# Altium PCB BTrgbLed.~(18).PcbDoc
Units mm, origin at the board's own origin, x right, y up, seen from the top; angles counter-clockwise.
Board outline 98.71 x 98.67 mm, 2 copper layers (Top Layer, Bottom Layer); 13 components, 12 nets, 62 pads, 4 vias.
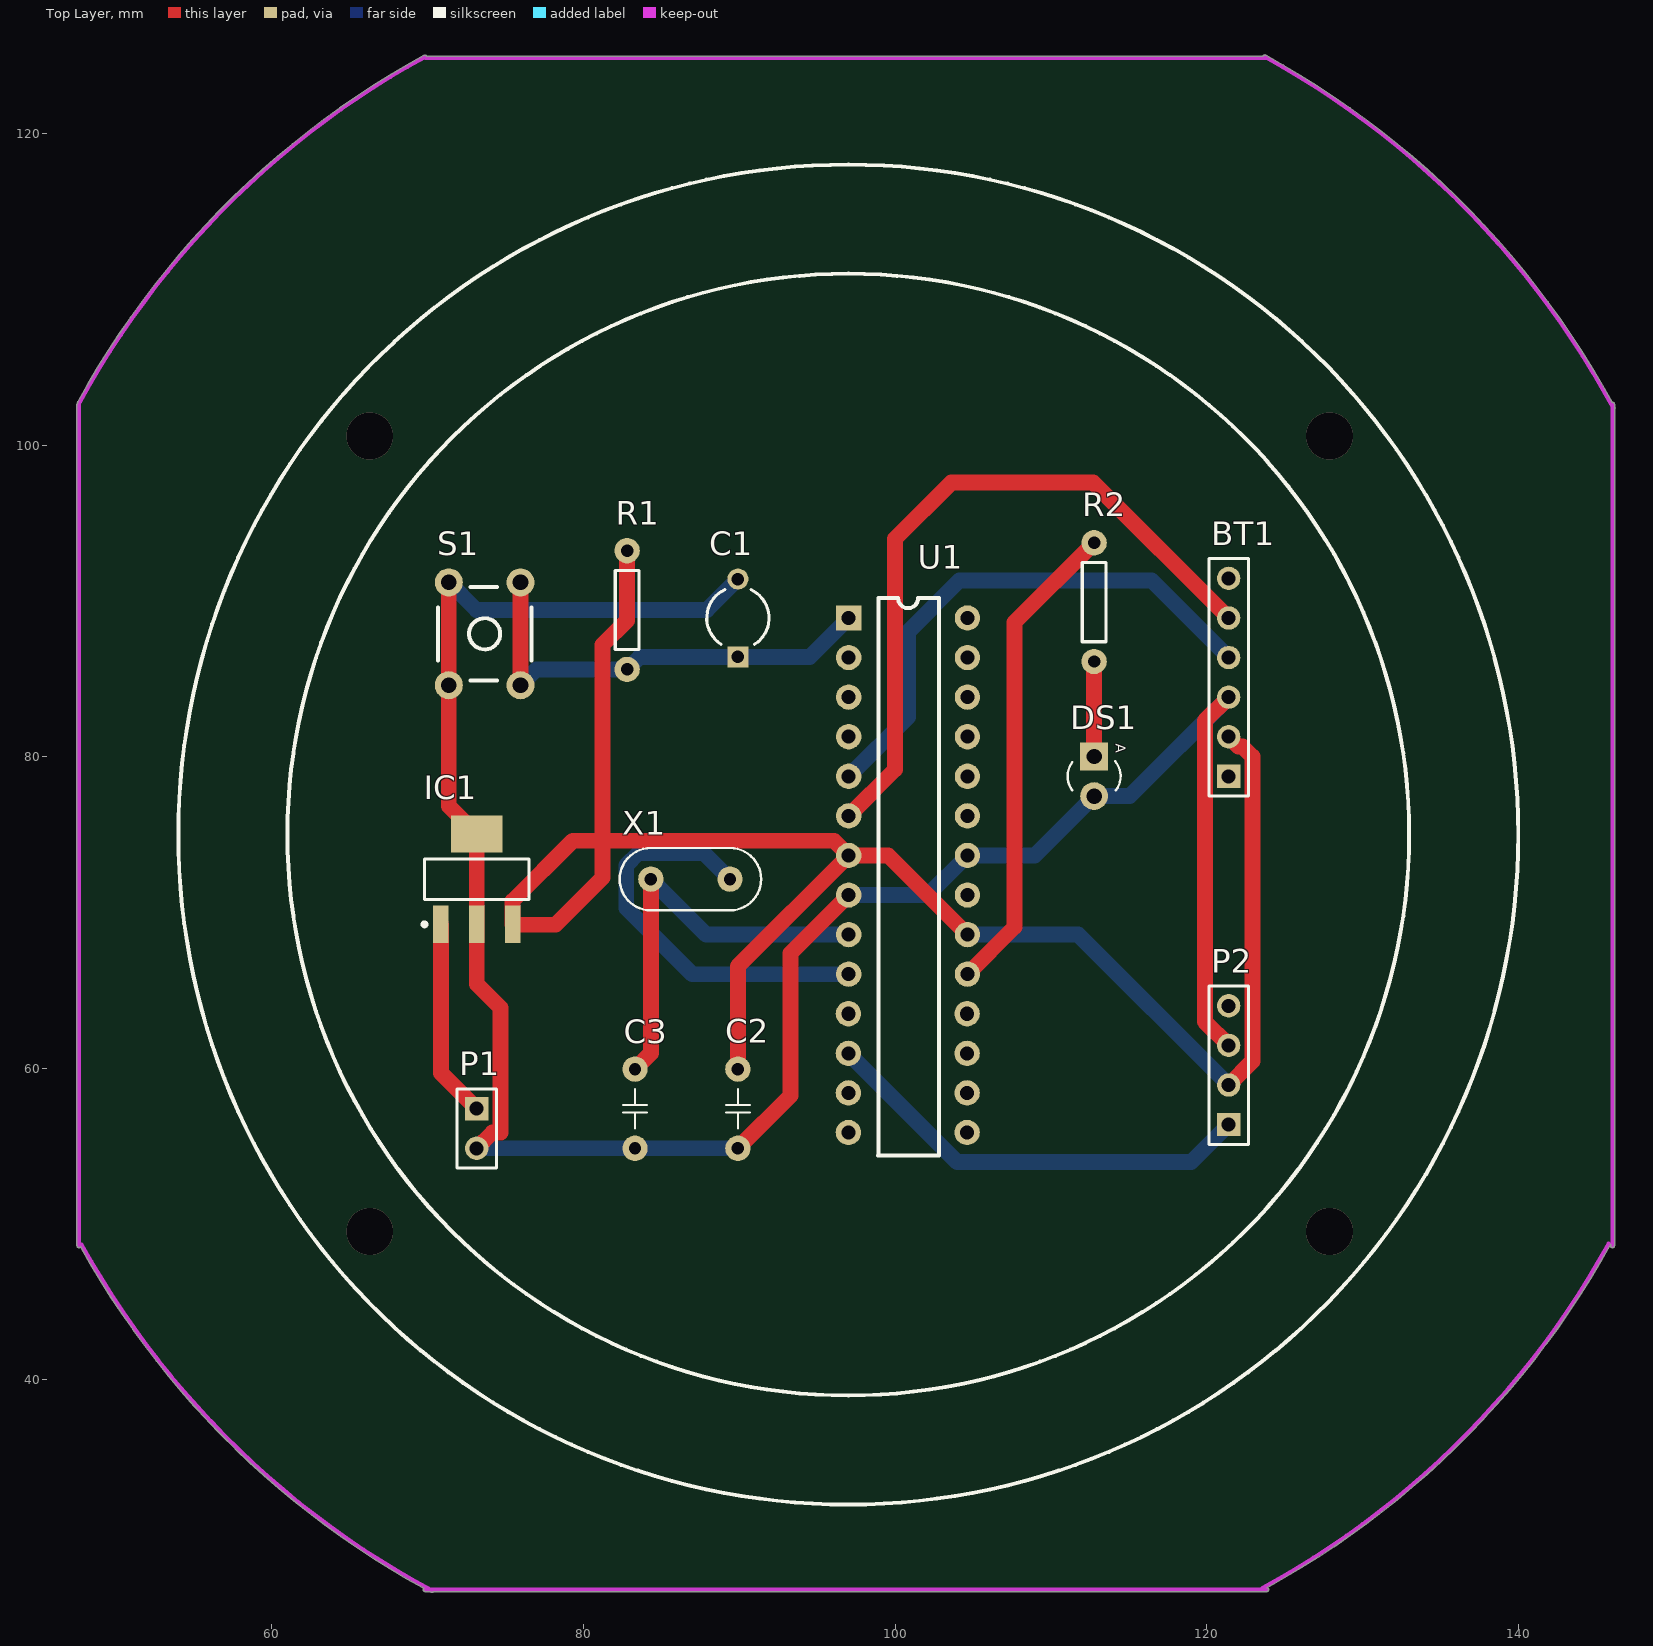
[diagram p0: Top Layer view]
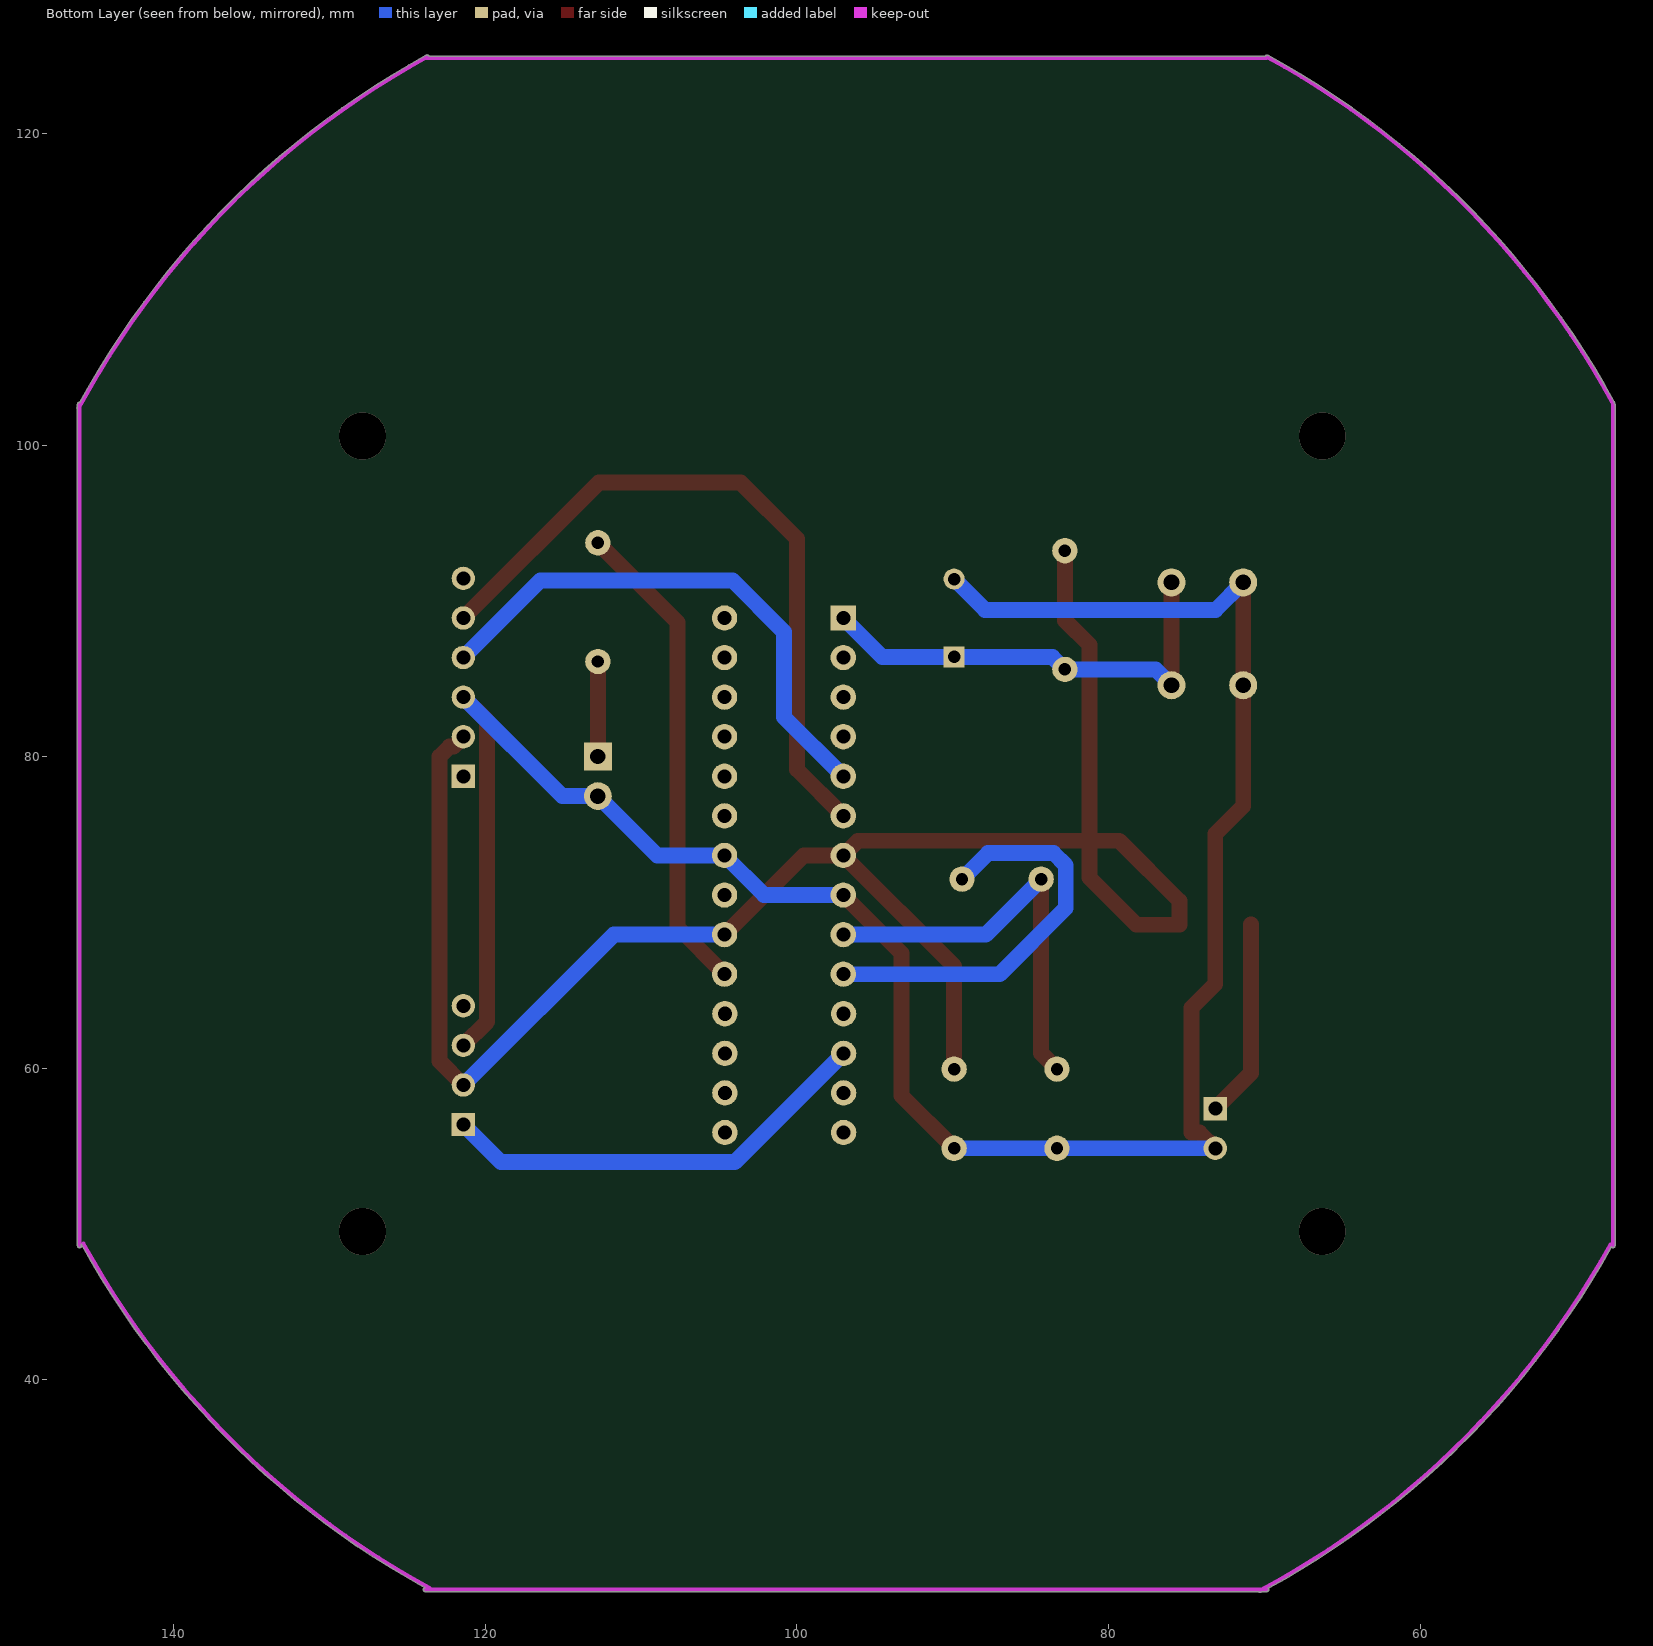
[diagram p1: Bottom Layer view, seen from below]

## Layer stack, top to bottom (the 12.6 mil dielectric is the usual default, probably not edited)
Top Layer: signal copper 0.0356
Dielectric: dielectric 0.32, FR-4, Dk 4.8
Bottom Layer: signal copper 0.0356

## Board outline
69.85,26.416 70.143,26.416 ccw(c96.781,75.819) 70.218,26.375 ccw(c70.279,26.487) 70.384,26.416 123.85,26.416 ccw(c123.85,26.543) 123.977,26.543 ccw(c123.85,26.543) 123.88,26.667 ccw(c96.781,75.819) 145.916,48.69 ccw(c145.805,48.751) 145.923,48.703 145.923,48.616 ccw(c146.05,48.616) 146.177,48.616 146.177,102.295 ccw(c146.082,102.379) 146.209,102.379 ccw(c146.082,102.379) 146.194,102.44 ccw(c96.781,75.819) 146.177,102.47 146.177,102.616 ccw(c146.05,102.616) 146.03,102.742 ccw(c96.781,75.819) 123.795,125.018 ccw(c123.734,124.906) 123.623,124.968 69.925,124.968 ccw(c69.817,124.9) 69.756,125.012 ccw(c96.781,75.819) 47.559,102.791 ccw(c47.671,102.73) 47.544,102.715 ccw(c47.625,102.616) 47.498,102.616 47.498,48.616 ccw(c47.625,48.616) 47.728,48.541 ccw(c96.781,75.819) 69.754,26.627 ccw(c69.85,26.543)

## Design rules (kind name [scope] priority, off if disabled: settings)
Clearance [All] p1: gap=0.254
PolygonConnect [All] p1: connectstyle=Relief reliefconductorwidth=0.254 reliefentries=4 polygonreliefangle="90 Angle"
RoutingVias [All] p1: holewidth=0.711 width=1.27 viastyle="Through Hole" minholewidth=0.711 minwidth=1.27 maxholewidth=0.711 maxwidth=1.27
SilkscreenOverComponentPads [All] p1: minsilkscreentomaskgap=0.254
SolderMaskExpansion [All] p1: expansion=0.102
Width [All] p1: maxlimit=1.27 minlimit=0.762 preferedwidth=1.016
27 further rules are at their usual default settings.

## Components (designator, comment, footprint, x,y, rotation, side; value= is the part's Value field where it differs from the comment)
BT1 "Bluetooth" Bluetooth 121.412,78.74 r90 top
C1 "47uF" CAPR5-4X5 89.916,88.9 r90 top
C2 "22pF" C200 89.916,57.404 r0 top
C3 "22pF" C200 83.312,57.404 r180 top
DS1 "TX-LED" LED-3mm_G 112.776,78.74 r270 top
IC1 "AM1117-5V" SOT-223 73.152,72.136 r90 top
P1 "12V" HDR1X2 73.152,57.404 r270 top
P2 "環形LED燈" HDR1X4 121.412,56.388 r90 top
R1 "10k" AXIAL-0.3 82.804,89.408 r270 top
R2 "220" AXIAL-0.3 112.776,89.916 r90 top
S1 "SW-PB" TACK6 73.66,87.884 r90 top
U1 "ATmega328" DIP-28 97.028,88.9 r270 top
X1 "16MHz" XTAL4-8 86.868,72.136 r0 top

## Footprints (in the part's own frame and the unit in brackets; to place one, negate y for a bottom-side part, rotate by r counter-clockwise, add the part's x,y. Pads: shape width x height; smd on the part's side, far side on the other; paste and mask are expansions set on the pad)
AXIAL-0.3 [mil] "0.3\" Resistor; 2 Leads"
  round 64 hole 31.5: 1(-150,0) 2(150,0)
  silkscreen extent -100,-30 100,30, body extent -161,-39 165,39, height 86
Bluetooth [mm]
  rect 1.5x1.5 hole 0.9: 1(0,0)
  round 1.5 hole 0.9: 2(2.54,0) 3(5.08,0) 4(7.62,0) 5(10.16,0) 6(12.7,0)
  silkscreen extent -1.27,-1.27 13.97,1.27, body extent -1.25,-1.3 13.97,1.28, height 11
C200 [mil] "塑膠電容器"
  round 64 hole 31.5: 1(0,100) 2(0,-100)
  silkscreen extent -30,-50 30,50, body extent -41,-136 39,135, height 354
CAPR5-4X5 [mm] "Capacitor; 2 Leads"
  rect 1.35x1.35 hole 0.8: 1(-2.5,0)
  round 1.35 hole 0.8: 2(2.5,0)
  silkscreen extent -1.69,-2 1.82,2
DIP-28 [mil]
  rect 64x64 hole 35.43: 1(0,0)
  round 64 hole 35.43: 2(100,0) 3(200,0) 4(300,0) 5(400,0) 6(500,0) 7(600,0) 8(700,0) 9(800,0) 10(900,0) 11(1000,-0.79) 12(1100,-0.79) 13(1200,-0.79) 14(1300,-0.79) 15(1300,299.21) 16(1200,299.21) 17(1100,299.21) 18(1000,299.21) 19(900,300) 20(800,300) 21(700,300) 22(600,300) 23(500,300) 24(400,300) 25(300,300) 26(200,300) 27(100,300) 28(0,300)
  silkscreen extent -50,74 1358,228, body extent -53,-5 1358,304, height 209
HDR1X2 [mm] "Connector; Header; 2 Position"
  rect 1.5x1.5 hole 0.9: 1(0,0)
  round 1.5 hole 0.9: 2(2.54,0)
  silkscreen extent -1.27,-1.27 3.81,1.27
HDR1X4 [mm] "Connector; Header; 4 Position"
  rect 1.5x1.5 hole 0.9: 1(0,0)
  round 1.5 hole 0.9: 2(2.54,0) 3(5.08,0) 4(7.62,0)
  silkscreen extent -1.27,-1.27 8.89,1.27
LED-3mm_G [mil] "3mm LED_Green"
  rect 70x70 hole 39: 1(-50,0)
  round 70 hole 39: 2(50,0)
  silkscreen extent -38,-67 35,67, body extent -66,-68 67,66, height 181
SOT-223 [mm] "SOT223, 4-Leads, Body 6.7x7.3mm (max), Pitch 2.30mm, IPC Medium Density"
  rect 2.4x1 smd: 1(-2.9,2.3) 2(-2.9,0) 3(-2.9,-2.3)
  rect 2.4x3.3 smd: 2(2.9,0)
  silkscreen extent -3.02,-3.35 1.3,3.47, body extent -1.86,-3.35 1.86,3.35, height 1.8
TACK6 [mm]
  round 1.8 hole 1: 1(-3.3,2.3) 1(3.3,2.3) 2(-3.3,-2.3) 2(3.3,-2.3)
  silkscreen extent -3,-3 3,3, body extent -3,-3.01 3.08,3.04, height 8
XTAL4-8 [mil]
  round 64 hole 31.5: 1(-100,0) 2(100,0)
  silkscreen extent -179,-79 179,79, body extent -178,-80 192,79, height 157

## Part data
C1: library part "Cap Pol1", "Polarized Capacitor (Radial)"
C2 C3: library part Cap, "Capacitor"
DS1: library part LED, "Typical INFRARED GaAs LED"
IC1: library part AM1117
P1: library part "Header 2", "Header, 2-Pin"
P2: library part "Header 4", "Header, 4-Pin"
R1 R2: library part Res, "Resistor"
S1: "Switch"
U1: "Arduino"
X1: library part XTAL, "Crystal Oscillator"

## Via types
v1: diameter 3, hole 3, Top Layer to Bottom Layer, 4 vias

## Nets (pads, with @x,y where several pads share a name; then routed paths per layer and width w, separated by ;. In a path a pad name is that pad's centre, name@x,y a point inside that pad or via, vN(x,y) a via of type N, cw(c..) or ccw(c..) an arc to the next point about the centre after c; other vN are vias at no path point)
DI: P2.1 U1.12 | length 28.3
  Bottom Layer w1.016: U1.12 103.993,53.975 118.999,53.975 P2.1
DO: P2.4
GND: BT1.3 C1.2 C2.2 C3.1 DS1.2 IC1.2 P1.2 P2.3 S1.1 U1.8 U1.22 | length 148
  Top Layer w1.016: S1.1@71.36,91.184 71.36,84.584 71.36,76.828 73.152,75.036 73.152,69.236 73.152,65.405 74.676,63.881 74.676,55.88 74.168,55.88 P1.2 ; C2.2 93.294,58.242 93.294,67.386 U1.8 ; P2.3 119.888,62.992 119.888,82.296 BT1.3
  Bottom Layer w1.016: S1.1@71.36,91.184 73.136,89.408 87.924,89.408 C1.2 ; P1.2 C3.1 C2.2 ; U1.8 102.108,71.12 U1.22 108.966,73.66 DS1.2 115.062,77.47 BT1.3
NetC1_1: C1.1 R1.2 S1.2 U1.1 | length 29.5
  Top Layer w1.016: S1.2@75.96,84.584 S1.2@75.96,91.184
  Bottom Layer w1.016: S1.2@75.96,84.584 76.974,85.598 R1.2 83.606,86.4 C1.1 94.528,86.4 U1.1
NetC2_2: U1.10 X1.2 | length 26.5
  Bottom Layer w1.016: X1.2 87.732,73.812 83.541,73.812 82.753,73.025 82.753,70.282 86.995,66.04 U1.10
NetC3_2: C3.2 U1.9 X1.1 | length 26.8
  Top Layer w1.016: C3.2 84.328,60.96 X1.1
  Bottom Layer w1.016: X1.1 87.884,68.58 U1.9
NetDS1_1: DS1.1 R2.1 | length 6.1
  Top Layer w1.016: DS1.1 R2.1
NetIC1_1: IC1.1 P1.1 | length 12.8
  Top Layer w1.016: IC1.1 70.852,59.704 P1.1
NetR2_2: R2.2 U1.19 | length 31.1
  Top Layer w1.016: U1.19 107.671,69.063 107.671,88.621 R2.2
RX: BT1.5 U1.6 | length 45.5
  Top Layer w1.016: U1.6 100,79.172 100,93.98 103.607,97.587 112.725,97.587 BT1.5
TX: BT1.4 U1.5 | length 34.8
  Bottom Layer w1.016: U1.5 100.838,82.55 100.838,88.011 104.14,91.313 116.459,91.313 BT1.4
VCC: BT1.2 C2.1 IC1.3 P2.2 R1.1 U1.7 U1.20 | length 124.7
  Top Layer w1.016: R1.1 82.804,88.748 81.229,87.173 81.229,74.6 ; C2.1 89.916,66.548 U1.7 ; U1.20 99.568,73.66 U1.7 ; P2.2 122.936,60.452 122.936,80.01 122.301,80.645 122.047,80.645 BT1.2 ; 81.229,74.6 96.088,74.6 U1.7 ; 81.229,74.6 79.313,74.6 75.452,70.739 IC1.3 75.452,69.215 78.207,69.215 81.229,72.238 81.229,74.6
  Bottom Layer w1.016: U1.20 111.76,68.58 P2.2
pads on no net: BT1.1 BT1.6 U1.2 U1.3 U1.4 U1.11 U1.13 U1.14 U1.15 U1.16 U1.17 U1.18 U1.21 U1.23 U1.24 U1.25 U1.26 U1.27 U1.28
copper on no net:
  other v1: 66.294,49.53 127.889,49.53 66.294,100.584 127.889,100.584

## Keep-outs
Keep-Out Layer:
  lines w0.254: 47.625,48.616 47.625,102.616 ; 47.671,102.73 cw(c96.781,75.819) 69.817,124.9 ; 47.783,48.704 ccw(c96.781,75.819) 70.279,26.487 ; 69.85,26.543 123.85,26.543 ; 69.85,124.841 123.85,124.841 ; 123.584,26.65 ccw(c96.781,75.819) 145.805,48.751 ; 123.734,124.906 cw(c96.781,75.819) 146.082,102.379 ; 146.05,48.616 146.05,102.616

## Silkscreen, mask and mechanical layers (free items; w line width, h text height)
Top Overlay:
  circle w0.254: c97,75 r36
  circle w0.254: c97,75 r43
